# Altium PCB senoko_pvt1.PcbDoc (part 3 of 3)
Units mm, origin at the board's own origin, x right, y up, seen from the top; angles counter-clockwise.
Board outline 124.5 x 41 mm, 4 copper layers (Top Layer, Internal Plane 1, Internal Plane 2, Bottom Layer), stack 1.671 mm thick; 226 components, 139 nets, 1479 pads, 355 vias.
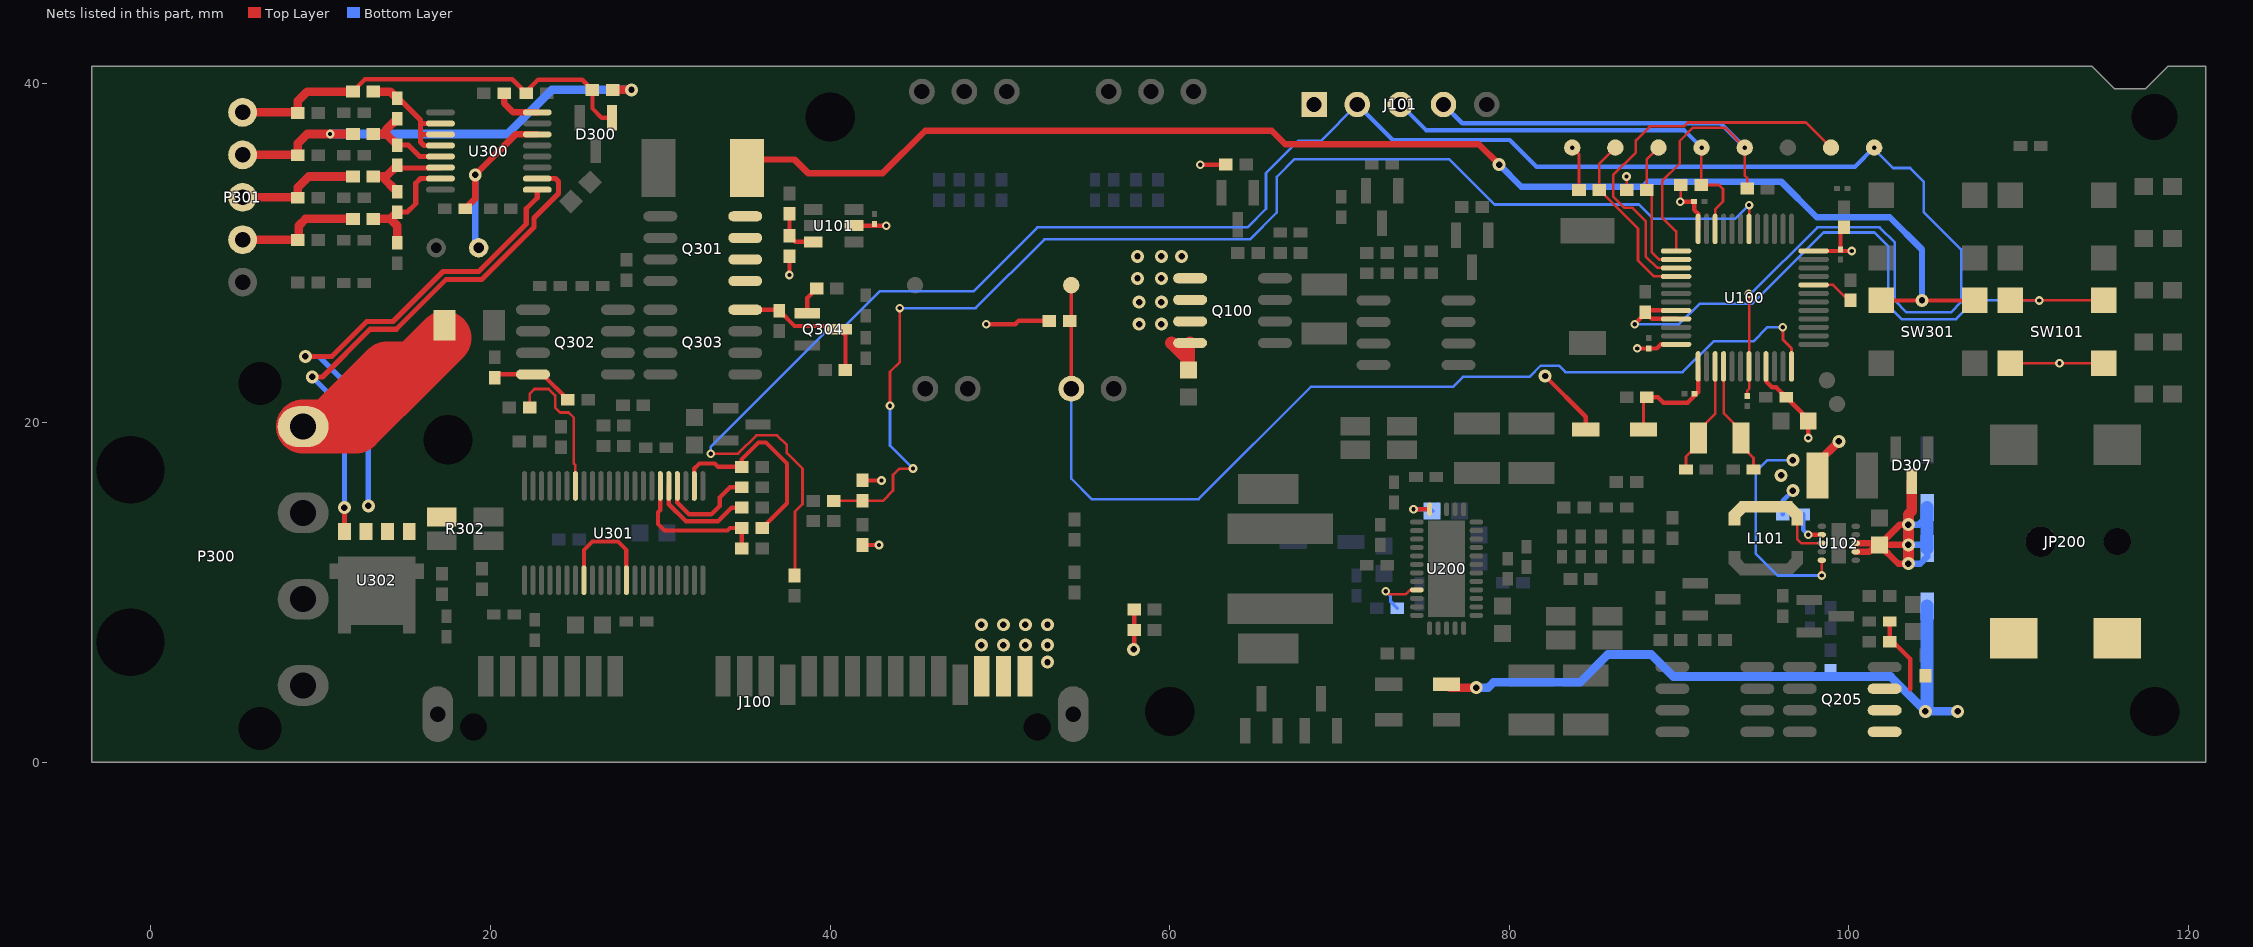
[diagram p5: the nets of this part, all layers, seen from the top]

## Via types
v1: diameter 0.508, hole 0.254, Top Layer to Bottom Layer, tented both sides, 187 vias
v2: diameter 0.762, hole 0.381, Top Layer to Bottom Layer, tented both sides, 155 vias
v3: diameter 0.66, hole 0.33, Top Layer to Bottom Layer, tented top, 9 vias
v4: diameter 0.5, hole 0.2, Top Layer to Bottom Layer, 3 vias
v5: diameter 0.66, hole 0.33, Top Layer to Bottom Layer, tented both sides, 1 vias

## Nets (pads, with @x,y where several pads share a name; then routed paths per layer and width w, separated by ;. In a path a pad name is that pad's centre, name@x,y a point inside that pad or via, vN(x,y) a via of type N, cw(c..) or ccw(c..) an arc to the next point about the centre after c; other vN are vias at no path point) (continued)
NetQ301_5: Q301.5 Q301.6 Q301.7 Q301.8 R300.1 SW301.1 SW301.2 | length 82.4
  Top Layer w0.254: SW301.2@101.9,27.2 SW301.1@107.4,27.2
  Top Layer w0.381: R300.1@35.1,35 35.4,35 35.9,35.5 37.9,35.5 38.7,34.7 43.1,34.7 45.6,37.2 66,37.2 66.8,36.4 78.2,36.4 v2(79.4,35.2)
  Bottom Layer w0.381: v2(79.4,35.2) 80.7,33.9 87.9,33.9 88.2,34.2 96,34.2 98.1,32.1 102.4,32.1 104.3,30.2 v2(104.3,27.2)
NetQ302_4: Q302.4 R303.2 R307.1 | length 5
  Top Layer w0.254: R303.2@20.25,22.65 20.445,22.845 Q302.4@22.5,22.845 23.065,22.845 24.55,21.36 R307.1@24.55,21.35
NetQ303_4: Q303.4 Q304.3 R304.1 R308.1 | length 8.6
  Top Layer w0.254: Q303.4@35,26.655 36.945,26.655 R304.1@37,26.6 37.9,25.7 40.35,25.7 Q304.3@40.55,25.5 40.9,25.15 R308.1@40.9,23.1
NetQ304_1: Q304.1 R311.1 | length 1.7
  Top Layer w0.254: Q304.1@38.65,26.45 38.65,27.35 R311.1@39.2,27.9
NetR102_2: R102.2 U102.7 | length 2.1
  Top Layer w0.254: v1(97.6,13.4) U102.7@98.4,13.4
  Bottom Layer w0.254: R102.2@97.3,14.6 97.3,13.7 v1(97.6,13.4)
NetR116_2: R116.2 U100.20 | length 2.6
  Top Layer w0.152: U100.20@97.917,28.114 99.061,28.114 99.975,27.2 R116.2@100.1,27.2
NetR117_2: R117.2 R118.1 U101.6 | length 2.8
  Top Layer w0.254: R118.1@37.6,32.3 R117.2@37.6,31 37.95,30.65 U101.6@39,30.65
NetR211_1: R211.1 U200.26 | length 3.3
  Top Layer w0.152: v1(72.725,10.075) 72.9,9.9 73.9,9.9 74.15,10.15 U200.26@74.55,10.15
  Bottom Layer w0.203: v1(72.725,10.075) 73,9.8 73,9.475 R211.1@73.4,9.075
NetR319_2: R319.2 R322.2 U301.2 | length 12.5
  Top Layer w0.254: U301.2@32,16.275 32,17.3 32.3,17.6 33.2,17.6 33.4,17.4 R319.2@34.8,17.4 34.8,17.854 35.779,18.833 36.221,18.833 37.458,17.596 37.458,15.258 R322.2@36,13.8
NetR320_2: R320.2 U301.4 | length 6
  Top Layer w0.254: U301.4@31,16.275 31,15.3 31.7,14.6 33,14.6 33.5,15.1 33.5,15.6 34.1,16.2 R320.2@34.8,16.2
NetR321_2: R321.2 U301.5 | length 6.1
  Top Layer w0.254: U301.5@30.5,16.275 30.5,15.2 31.506,14.194 33.394,14.194 34.2,15 R321.2@34.8,15
NetR322_1: R322.1 R323.1 U301.6 | length 8.7
  Top Layer w0.254: U301.6@30,16.275 30,14.854 29.867,14.721 29.867,14.033 30.25,13.65 33.95,13.65 34.1,13.8 R322.1@34.8,13.8 R323.1@34.8,12.6
NetR338_2: R338.2 U301.16 | length 8.7
  Top Layer w0.152: R338.2@22.3,20.9 22.3,21.7 22.583,21.983 23.425,21.983 23.8,21.607 23.8,20.9 24.1,20.6 24.6,20.6 24.9,20.3 24.9,17.6 25,17.5 U301.16@25,16.275
NetR339_1: R339.1 U300.16 | length 2.8
  Top Layer w0.381: R339.1@20.8,39.4 20.8,38.8 21.325,38.275 U300.16@22.75,38.275
NetU301_30: U301.30 U301.35 | length 6.5
  Top Layer w0.254: U301.30@25.5,10.725 25.5,12.5 26,13 27.5,13 28,12.5 U301.35@28,10.725
P2_CD: C309.1 J300.1 U300.14 | length 11.3
  Top Layer w0.381: C309.1@18.5,32.6 19.1,33.2 v2(19.1,34.6) 21.475,36.975 U300.14@22.75,36.975
  Bottom Layer w0.381: v2(19.1,34.6) 19.1,30.7 J300.1@19.5,30.3
P2_OUT: U300.10 U302.4 | length 31.2
  Top Layer w0.305: v2(9.5,22.7) 10.1,22.7 12.9,25.5 14.447,25.5 17.389,28.443 19.489,28.443 22.557,31.511 22.557,32.057 24,33.5 24,34.2 23.825,34.375 U300.10@22.75,34.375 ; U302.4@11.395,13.595 v2(11.395,14.995)
  Bottom Layer w0.305: v2(9.5,22.7) 11.395,20.805 v2(11.395,14.995)
P2_PCKN: R302.2 U300.9 U302.1 U302.2 U302.3 | length 29.3
  Top Layer w0.305: v2(9.1,23.9) 10.653,23.9 12.711,25.957 14.257,25.957 17.2,28.9 19.3,28.9 22.1,31.7 22.1,32.6 22.75,33.25 U300.9@22.75,33.725
  Bottom Layer w0.305: v2(9.1,23.9) 9.9,23.9 12.8,21 v2(12.8,15.1)
P2_VC1: C304.1 R306.2 U300.2 U300.3 U300.4 | length 8.4
  Top Layer w0.305: C304.1@14.5,39.1 14.6,39.1 15.875,37.825 15.875,37.625 ; U300.4@17.05,36.325 16.075,36.325 15.875,36.525 15.875,37 ; U300.3@17.05,36.975 15.9,36.975 15.875,37 ; U300.2@17.05,37.625 15.875,37.625 ; 15.875,37 15.875,37.625
  Top Layer w0.508: R306.2@13.1,39.5 14.1,39.5 C304.1@14.5,39.1
P2_VC2: C304.2 C306.1 R310.2 U300.5 | length 5.7
  Top Layer w0.305: C306.1@14.5,36.35 15.15,36.35 15.825,35.675 U300.5@17.05,35.675
  Top Layer w0.508: R310.2@13.1,37 13.85,37 ; C306.1@14.5,36.35 13.85,37 ; C304.2@14.5,37.9 13.85,37.25 13.85,37
P2_VC3: C306.2 C308.1 R312.2 U300.6 | length 5.1
  Top Layer w0.305: C306.2@14.5,35.15 14.65,35 17.025,35 U300.6@17.05,35.025
  Top Layer w0.508: C308.1@14.5,33.6 13.6,34.5 13.85,34.5 C306.2@14.5,35.15
P2_VC4: C308.2 C311.1 R318.2 U300.7 | length 7.2
  Top Layer w0.305: C308.2@14.5,32.4 15.1,32.4 15.6,32.9 15.6,34.1 15.875,34.375 U300.7@17.05,34.375
  Top Layer w0.508: R318.2@13.1,32 14.1,32 ; C311.1@14.5,30.6 14.5,31.6 14.1,32 ; C308.2@14.5,32.4 14.1,32
P3.3V_UC: C102.1 C103.1 C104.1 C112.2 C113.2 C115.1 C118.1 C222.1 D100.1 J101.1 L101.2 R102.1 R108.1 R109.2 R110.2 R111.2 R112.2 R113.2 R117.1 R119.2 R121.2 R225.1 R226.1 SW101.1 SW101.2 TP100.1 U100.9 U100.24 U100.36 U100.48 U101.2 U102.8 U102.10 U200.17 | length 62.4
  Top Layer w0.152: v1(83.7,36.2) 84.1,35.8 R113.2@84.1,33.7 ; R112.2@86.9,33.7 v1(86.9,34.5) ; v1@90.05,33.025 90.1,33.075 R111.2@90.1,34 ; L101.2@96.95,14.325 96.95,13.15 97.2,12.9 U102.8@98.4,12.9 ; v1(98.4,11) U102.10@98.4,11.9 ; SW101.1@109.5,23.5 SW101.2@115,23.5
  Top Layer w0.254: v1@37.575,28.675 v1(37.6,28.7) R117.1@37.6,29.8 ; U101.2@41.4,31.6 v1(43.3,31.6) ; R109.2@41.9,12.8 v1(42.875,12.8) ; R110.2@41.9,16.6 v1(43.025,16.6) ; v1(49.2,25.8) 50.9,25.8 51.1,26 R121.2@52.9,26 ; v2(57.875,6.65) 57.9,6.675 R225.1@57.9,7.8 R226.1@57.9,9 ; v1(61.8,35.2) R108.1@63.3,35.2 ; v1(74.35,14.9) U200.17@75.3,14.9 ; v2(82.1,22.75) 84.5,20.35 D100.1@84.5,19.6 D100.1@84.775,19.6 ; v1(87.525,24.375) 88.675,24.375 88.914,24.614 U100.48@89.817,24.614 ; v1@90.05,33.025 v1(90.055,33.02) C103.1@90.88,33.02 90.88,32.545 91.117,32.308 U100.36@91.117,31.414 ; U100.9@95.117,23.314 95.117,22.438 95.475,22.079 95.721,22.079 C112.2@96.3,21.5 97.6,20.2 C113.2@97.6,20.1 v1(97.6,19.1) ; U100.24@97.917,30.114 v1(100.164,30.114) v1@100.175,30.125 ; C104.1@99.5,30.2 R119.2@99.5,31.3
  Top Layer w0.508: C118.1@98.15,16.9 98.15,17.65 v2(99.4,18.9)
  Bottom Layer w0.152: v2(96.7,17.8) 95.2,17.8 94.5,17.1 94.5,12.3 95.8,11 v1(98.4,11)
  Bottom Layer w0.254: v1(74.35,14.9) 75.35,14.9 C222.1@75.45,14.8 ; R102.1@96.1,14.6 96.1,15.4 v2(96.7,16)
  other v1: 112.4,23.5
  other v2: 96,16.9
PM_JRST: R113.1 TP101.1 U100.40 | length 10.6
  Top Layer w0.152: TP101.1@86.24,36.2 85.3,35.26 R113.1@85.3,33.7 87.575,31.425 87.575,29.55 88.511,28.614 U100.40@89.817,28.614
PM_JTCK: J101.4 R114.2 TP104.1 U100.37 | length 33.1
  Top Layer w0.152: U100.37@89.817,30.114 89.817,31.258 89,32.075 89,34.225 90.025,35.25 90.025,36.575 90.825,37.375 92.685,37.375 v1(93.86,36.2) 93.86,34.565 94,34.425 R114.2@94,33.8
  Bottom Layer w0.254: J101.4@76.12,38.74 77.224,37.636 92.424,37.636 v1(93.86,36.2)
PM_JTDI: R112.1 TP102.1 U100.38 | length 8.2
  Top Layer w0.152: TP102.1@88.78,36.2 88.1,35.52 R112.1@88.1,33.7 88.375,33.425 88.375,30.05 88.811,29.614 U100.38@89.817,29.614
PM_JTDO: TP105.1 U100.39 | length 23.1
  Top Layer w0.152: U100.39@89.817,29.114 88.711,29.114 88.025,29.8 88.025,31.875 87.25,32.65 86.781,32.65 86.116,33.316 86.116,34.591 87.45,35.925 87.45,36.625 88.275,37.45 90.275,37.45 90.505,37.68 97.46,37.68 TP105.1@98.94,36.2
PM_JTMS: J101.3 R111.1 TP103.1 U100.34 | length 24.9
  Top Layer w0.152: v1(91.32,36.2) 91.3,36.18 R111.1@91.3,34 92.35,34 92.583,33.767 92.583,33.033 92.125,32.575 92.125,31.422 U100.34@92.117,31.414
  Bottom Layer w0.254: J101.3@73.58,38.74 75.091,37.229 90.291,37.229 v1(91.32,36.2)
PM_NRST: C114.1 J101.2 R103.1 TP106.1 U100.7 | length 130.1
  Top Layer w0.152: v1(32.975,18.175) 34.575,18.175 35.65,19.25 36.875,19.25 37.45,18.675 37.45,18.218 38.371,17.296 38.371,15.202 37.93,14.761 R103.1@37.93,11.087 ; C114.1@94.008,21.582 94.008,21.883 94.117,21.992 U100.7@94.117,23.314 94.117,27.583 v1(94.1,27.6)
  Bottom Layer w0.152: v1(32.975,18.175) 32.975,18.595 39.96,25.58 40.755,25.58 42.91,27.735 48.446,27.735 52.212,31.5 64.565,31.5 65.665,32.6 65.665,34.703 67.563,36.6 68.9,36.6 J101.2@71.04,38.74 ; v1(94.1,27.6) 94.23,27.6 98.135,31.505 101.795,31.505 102.7,30.6 102.7,27.2 103.4,26.5 106,26.5 106.6,27.1 106.6,30.2 104.4,32.4 104.4,34.2 103.6,35 102.6,35 101.48,36.12 v1(101.48,36.2)
  Bottom Layer w0.254: J101.2@71.04,38.74 73.13,36.65 80.025,36.65 81.6,35.075 100.355,35.075 v1(101.48,36.2)
PM_OSC32_IN: C110.1 U100.3 Y100.2 | length 7
  Top Layer w0.152: C110.1@90.273,17.252 C110.1@90.4,17.252 ; C110.1@90.4,17.25 C110.1@90.4,17.252 ; C110.1@90.512,17.252 C110.1@90.4,17.252 ; U100.3@92.117,23.314 92.117,20.517 91.15,19.55 Y100.2@91.15,19.1 91.15,18.75 90.4,18 C110.1@90.4,17.252
PM_OSC32_OUT: C111.1 U100.4 Y100.1 | length 6.8
  Top Layer w0.152: U100.4@92.617,23.314 92.617,20.583 93.65,19.55 Y100.1@93.65,19.1 93.65,18.65 94.375,17.925 C111.1@94.375,17.25 ; C111.1@94.223,17.286 C111.1@94.257,17.252
PM_REFLASH_ALRT: R106.2 SW101.3 SW101.4 U100.44 U100.45 | length 41
  Top Layer w0.152: SW101.3@109.5,27.2 SW101.4@115,27.2
  Top Layer w0.254: v1(87.375,25.8) 88,26.425 R106.2@88,26.5 ; U100.45@89.817,26.114 88.386,26.114 R106.2@88,26.5 ; U100.44@89.817,26.614 88.114,26.614 R106.2@88,26.5
  Bottom Layer w0.152: v1(87.375,25.8) 90,25.8 91.2,27 94.3,27 98.5,31.2 101.5,31.2 102.3,30.4 102.3,26.9 103.1,26.1 106.3,26.1 107.4,27.2 v1(111.2,27.2)
PM_TO_HOST_UART: R100.1 R110.1 U100.30 | length 74.3
  Top Layer w0.152: R100.1@40.2,15.4 R110.1@41.9,15.4 43.1,15.4 43.7,16 43.7,16.925 44.075,17.3 v1(44.875,17.3) ; v1(43.525,21) 43.525,23 44.1,23.575 v1(44.1,26.75) ; U100.30@94.117,31.414 v1(94.117,32.817)
  Bottom Layer w0.152: v1(43.525,21) 43.525,18.65 v1(44.875,17.3) ; v1(44.1,26.75) 48.569,26.75 52.619,30.8 64.728,30.8 66.3,32.372 66.3,34.475 67.35,35.525 76.45,35.525 79.125,32.85 87.625,32.85 88.475,32 93.3,32 v1(94.117,32.817)
PM_VBAT: C109.1 D100.2 R107.2 U100.1 | length 7
  Top Layer w0.152: D100.2@87.9,19.6 87.9,21.3 R107.2@88.1,21.5 ; C109.1@90.914,21.658 C109.1@90.914,21.707
  Top Layer w0.254: R107.2@88.1,21.5 88.75,21.5 89.08,21.17 90.497,21.17 91.117,21.789 U100.1@91.117,23.314
PWR_TO_HOST: C101.1 J100.1 J100.2 J100.3 Q100.5 Q100.6 Q100.7 Q100.8 | length 3.1
  Top Layer w0.762: 60.1,24.7 61.1,23.7 ; C101.1@61.1,23.1 61.1,23.7 ; Q100.8@61.2,24.695 61.1,24.595 61.1,23.7
  other v2: 52.8,5.9 48.9,6.9 50.2,6.9 51.5,6.9 52.8,6.9 48.9,8.1 50.2,8.1 51.5,8.1 52.8,8.1 58.2,25.8 59.5,25.8 58.2,27.1 59.5,27.1 58.1,28.5 59.5,28.5 58.1,29.8 59.5,29.8 60.7,29.8
RAW_ACIN: C204.2 D101.1 D201.1 JP200.1 Q205.1 Q205.2 Q205.3 R208.1 R213.1 R214.1 | length 43.2
  Top Layer w0.254: C204.2@102.4,8.3 R208.1@102.4,7.1 102.6,7.1 103.6,6.1 103.6,4.3
  Top Layer w0.508: D201.1@76.3,4.6 76.5,4.4 v2(78.05,4.4)
  Bottom Layer w0.508: v2(78.05,4.4) 78.756,4.4 79.063,4.707 84.157,4.707 85.8,6.35 88.35,6.35 89.65,5.05 102.45,5.05 v2(104.5,3) v2(106.4,3)
  Bottom Layer w0.762: v2(104.5,3) 104.6,3.1 D101.1@104.6,9.2
UC_BOOTSTRAP: C117.1 D101.2 D307.3 D308.2 U102.2 U102.3 | length 20.9
  Top Layer w0.381: U102.2@100.4,12.4 101.2,12.4 101.7,12.9 U102.3@100.4,12.9 ; v2(103.5,11.7) 102.9,11.7 C117.1@101.8,12.8 ; v2(103.5,12.8) C117.1@101.8,12.8 ; v2(103.5,14) 103,14 C117.1@101.8,12.8
  Top Layer w0.635: v2(103.5,11.7) v2(103.5,14) 103.5,14.6 103.7,14.8 D307.3@103.7,16.55
  Bottom Layer w0.381: v2(103.5,11.7) 104.2,11.7 104.6,12.1 D101.2@104.6,12.6 104.4,12.8 v2(103.5,12.8) ; v2(103.5,14) 104.1,14 104.6,14.5 D308.2@104.6,15
  Bottom Layer w0.762: D101.2@104.6,12.6 D308.2@104.6,15
USART2_TX_ADC2: J103.1 P102.1 R121.1 U100.12 | length 60.8
  Top Layer w0.178: v1(96.1,25.614) 96.1,24.9 96.617,24.383 U100.12@96.617,23.314
  Top Layer w0.203: P102.1@54.2,22 J103.1@54.2,28.1
  Bottom Layer w0.152: P102.1@54.2,22 54.2,16.7 55.4,15.5 61.693,15.5 68.302,22.109 76.678,22.109 77.264,22.695 81.183,22.695 81.847,23.36 82.917,23.36 83.3,22.976 90.207,22.976 92.026,24.795 94.364,24.795 95.183,25.614 v1(96.1,25.614)
VBAT: F300.1 P300.1 | length 17
  Top Layer w3.175: P300.1@8.96,19.77 10.47,19.77 ; F300.1@17.3,25 15.5,23.2 ; 10.47,19.77 12.07,19.77 15.5,23.2 ; 10.47,19.77 13.9,23.2 15.5,23.2
VC1: D300.1 P301.1 R305.2 R306.1 R309.1 R313.1 | length 25.3
  Top Layer w0.254: R306.1@11.9,39.5 11.9,39.521 12.6,40.221 21.279,40.221 R309.1@22.1,39.4 22.1,39.5 22.8,40.2 25.4,40.2 R305.2@26,39.6 26,38.5 26.55,37.95 D300.1@27.15,37.95
  Top Layer w0.508: P301.1@5.4,38.275 8.625,38.275 R313.1@8.65,38.25 8.65,38.95 9.2,39.5 R306.1@11.9,39.5
VC2: P301.2 R305.1 R310.1 R314.1 | length 27.4
  Top Layer w0.508: P301.2@5.4,35.775 8.625,35.775 R314.1@8.65,35.75 8.65,36.45 9.2,37 v1(10.55,37) R310.1@11.9,37 ; R305.1@27.2,39.6 v2(28.3,39.6)
  Bottom Layer w0.508: v1(10.55,37) 21,37 23.6,39.6 v2(28.3,39.6)
VC3: P301.3 R312.1 R315.1 | length 7.4
  Top Layer w0.508: P301.3@5.4,33.275 8.625,33.275 R315.1@8.65,33.25 8.65,33.85 9.3,34.5 R312.1@11.9,34.5
VC4: P301.4 R316.1 R318.1 | length 7.5
  Top Layer w0.508: P301.4@5.4,30.775 8.625,30.775 R316.1@8.65,30.75 8.7,30.8 8.7,31.6 9.1,32 R318.1@11.9,32
pads on no net: D300.2 D301.2 D307.2 J100.0 J100.7 J100.8 J100.9 JP200.0 P300.0 P300.4 U100.2 U100.5 U100.6 U100.11 U100.13 U100.15 U100.19 U100.26 U100.41 U100.42 U100.43 U100.46 U300.1 U300.11 U300.15 U301.12 U301.17 U301.19

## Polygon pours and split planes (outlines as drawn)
GND on Bottom Layer "bottom - GND" (solid, remove dead copper, pour order 2): 111.875,43.625 1.375,43.625 -5.8,42.4 -5.2,-2 0.925,-3.05 120.875,-3.05 124.8,0.875 124.8,39.975 121.25,43.525 111.15,43.525
GND on Top Layer "bottom - GND" (solid, remove dead copper, pour order 4): 90.45,-3.225 119.475,-3.225 124.375,1.675 124.375,42 121.775,44.6 1.65,44.6 -7,41.8 -7.6,-2.2 0.75,-4.475 1.9,-3.325 91.875,-3.325
GND on Internal Plane 1 (split plane): 87.321,14.357 87.321,13.868 87.182,13.729 86.793,13.729 86.604,13.918 86.604,14.282 86.818,14.496 87.182,14.496
GND on Internal Plane 1 (split plane): 82.021,12.957 82.021,12.568 81.732,12.279 81.493,12.279 81.179,12.593 81.179,12.882 81.389,13.093 81.886,13.093
GND on Internal Plane 1 (split plane): 76.396,17.657 76.396,16.45 76.396,15.443 75.127,14.173 75.104,14.14 75.096,14.1 75.096,9.925 75.104,9.885 75.127,9.852 75.427,9.552 75.46,9.529 75.5,9.521 75.882,9.521 76.221,9.182 76.221,8.618 75.957,8.354 70.743,8.354 69.254,9.843 69.254,11.5 69.254,14.532 72.893,18.171 75.882,18.171
GND on Internal Plane 1 (split plane): 37.521,18.157 37.521,12.368 36.607,11.454 34.75,11.454 34.71,11.446 34.677,11.423 30.282,7.029 28.743,7.029 27.348,8.423 27.315,8.446 27.275,8.454 18.275,8.454 18.235,8.446 18.202,8.423 16.532,6.754 15.493,6.754 15.229,7.018 15.229,8.282 18.293,11.346 20.4,11.346 20.408,11.348 21.55,11.348 21.589,11.356 21.622,11.378 22.272,12.028 22.294,12.061 22.302,12.1 22.302,13.205 23.118,14.021 26.15,14.021 26.19,14.029 26.223,14.052 27.723,15.552 27.734,15.569 27.746,15.585 27.754,15.625 27.754,20.557 28.968,21.771 33.907,21.771
GND on Internal Plane 1 (split plane): 120.49,0.51 -2.99,0.51 -2.99,40.49 114.089,40.49 115.264,39.314 115.341,39.251 115.43,39.203 115.525,39.174 115.625,39.165 117.475,39.165 117.575,39.174 117.67,39.203 117.759,39.251 117.836,39.314 119.011,40.49 120.49,40.49
no net on Internal Plane 2 (split plane): 98.998,11.258 98.998,10.742 98.758,10.502 98.142,10.502 97.902,10.742 97.902,11.258 98.142,11.498 98.758,11.498
CHG_SYS on Internal Plane 2 (split plane): 72.477,25.877 72.494,25.866 72.51,25.854 72.55,25.846 77.482,25.846 82.027,21.302 82.044,21.291 82.06,21.279 82.1,21.271 84.532,21.271 85.296,20.507 85.296,17.4 85.304,17.36 85.327,17.327 86.121,16.532 86.121,14.918 85.077,13.873 85.054,13.84 85.046,13.8 85.046,10.225 85.054,10.185 85.077,10.152 87.546,7.682 87.546,4.943 87.082,4.479 78.975,4.479 78.935,4.471 78.902,4.448 77.882,3.429 75.543,3.429 74.429,4.543 74.429,7.482 74.948,8.002 74.959,8.019 74.971,8.035 74.979,8.075 74.979,15.025 74.971,15.065 74.948,15.098 74.623,15.423 74.59,15.446 74.55,15.454 71.718,15.454 64.904,22.268 64.904,24.757 67.493,27.346 71.007,27.346
PWR_TO_HOST on Internal Plane 2 (split plane): 62.446,29.432 62.446,22.418 55.302,15.273 55.279,15.24 55.271,15.2 55.271,7.168 53.307,5.204 48.468,5.204 48.329,5.343 48.329,11.532 49.823,13.027 49.846,13.06 49.854,13.1 49.854,27.482 53.093,30.721 61.157,30.721
P3.3V_UC on Internal Plane 2 (split plane): 120.49,0.51 -2.99,0.51 -2.99,40.49 114.089,40.49 115.264,39.314 115.341,39.251 115.43,39.203 115.525,39.174 115.625,39.165 117.475,39.165 117.575,39.174 117.67,39.203 117.759,39.251 117.836,39.314 119.011,40.49 120.49,40.49

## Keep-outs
Keep-Out Layer:
  the board outline again, w1
  text "Route board on centerline of this outline" at 98.2,-3.1 h0.76

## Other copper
Top Layer:
  rectangle net P2_PCKN: 12.3,13.9 16.6,15.6
  rectangle net BAT_PGND: 9,8 12.3,12.2
  rectangle net NetL200_2: 64.1,14.1 67.5,15.6
  rectangle net NetC300_2: 20.2,23.8 22.2,27
  rectangle net NetD301_1: 27.8,22.5 29.7,27
  rectangle net NetD301_1: 30.5,22.5 33.2,27
  rectangle net NetD301_1: 31.3,26.9 33.2,32.4
  rectangle net NetD301_1: 30,29.4 32.3,32.4
  rectangle net NetQ301_5: 34.3,28.1 36.6,36.7
  rectangle net GND: 18.4,13.8 22.1,16.5
  rectangle net GND: 21,12.6 23.3,15.1
  rectangle net GND: 20,15.4 22.1,17.8
  rectangle net BAT_PROTECTED: 35,22.5 38.8,25.4
  rectangle net RAW_ACIN: 108.3,2.7 114.9,8.3
  rectangle net NetQ205_5: 94.6,1.5 97.2,5.9
  rectangle net CHG_SYS: 81.3,4.6 84.5,6.9
  rectangle net CHG_SYS: 80.3,5.5 81.9,9.7
  rectangle net CHG_SYS: 78.3,9 79.2,10.2
  rectangle net CHG_SYS: 79.1,8.6 81.1,9.7
  rectangle net GND: 78.9,0.7 86.8,4.2
  rectangle net NetC206_2: 64,7.1 74.55,9.65
  rectangle net NetC206_2: 74.1,7.1 75.9,7.8
  rectangle net BAT_PROTECTED: 76.9,19.8 79.3,27.5
  rectangle net BAT_PROTECTED: 72.8,19.6 82.7,21.4
  rectangle net CHG_SYS: 66.7,24.375 71.9,27.2
  rectangle net CHG_SYS: 66.7,24.4 67.4,27.5
  rectangle net PWR_TO_HOST: 57.6,24.4 61.2,30.4
  rectangle net GND: 76.6,16.1 84.7,18.8
  rectangle net GND: 78.7,15.2 82,16.6
  rectangle net GND: 44.7,5.6 48.1,8.8
  rectangle net GND: 37,5.6 40.5,8.8
  rectangle net PWR_TO_HOST: 48.5,5.5 53.3,8.6
  rectangle net GND: 106.9,17.1 118.8,20.9
  rectangle net GND: 76.15,6.1 80.1,8.1
  rectangle net GND: 78,7.65 78.925,8.8
  rectangle net GND: 76.15,5.275 79.75,6.325
  rectangle net GND: 76.15,7.9 78.1,8.8
  rectangle net CHG_SYS: 67.175,22.95 70.75,25.15
  rectangle net CHG_SYS: 65.175,22.95 67.375,24.675
  rectangle net P3.3V_UC: 95.6,14.7 97.6,18.2
  rectangle net RAW_ACIN: 102.1,1.3 114.9,4.8
  rectangle net RAW_ACIN: 105.3,4.4 108.7,6.2
  rectangle net NetC205_2: 86.2,5.6 89.3,7.7
  rectangle net NetC205_2: 87.2,2.5 89.3,6.1
  pour cut-out: 74.45,18.2 72.875,18.2 69.125,14.45 69.125,9.65 70.65,8.125 87.875,8.125 90.675,10.925 90.675,15.15 90.25,15.575 82.825,15.575 82.075,14.825 77.35,14.825 76.325,15.85 76.325,17.775 75.825,18.275 75.775,18.225 74,18.225
  pour cut-out: 15.1,6.975 15.475,6.6 17.425,6.6 18.025,7.2 32.45,7.2 37.45,12.2 37.45,18.15 33.85,21.75 28.825,21.75 27.45,20.375 27.45,15.4 26.35,14.3 24.5,14.3 24.025,13.825 24.025,12.725 23.475,12.175 16.4,12.175 15.1,10.875
  pour cut-out: 29.5,40 29.5,38.7 33,38.7 33,40
  text "1" at 29.8,39 h0.76
Bottom Layer:
  pour cut-out: 88.9,8.4 90.775,10.275 90.775,15.075 90.325,15.525 86.325,15.525 85.525,14.725 78.875,14.725 76.3,17.3 76.3,17.775 75.85,18.225 73.125,18.225 69.2,14.3 69.2,9.625 70.425,8.4
  pour cut-out: 33.7,21.775 28.825,21.775 23.7,16.65 23.7,12.8 23,12.1 16.5,12.1 14.975,10.575 14.975,7.1 15.525,6.55 17.35,6.55 18,7.2 32.175,7.2 37.5,12.525 37.5,18.125 33.875,21.75 33.55,21.75
  pour cut-out: 29.5,38.7 33,38.7 33,40 29.5,40
  text "4" at 32.2,39 h0.76
Internal Plane 1 (plane layer: these items are gaps in the copper):
  rectangle: 29.5,38.7 30.2,40
  rectangle: 31.1,38.7 33,40
  lines w0.2: 20.4,11.45 21.55,11.45 22.2,12.1 22.2,13.25
  lines w0.203: 20.4,11.45 18.25,11.45 15.125,8.325 15.125,6.975 15.45,6.65 16.575,6.65 18.275,8.35 24.95,8.35 27.275,8.35 28.7,6.925 30.325,6.925 34.75,11.35 36.65,11.35 37.625,12.325 37.625,18.2 33.95,21.875 28.925,21.875 27.65,20.6 27.65,15.625 26.15,14.125 23.075,14.125 22.2,13.25 ; 69.15,9.8 69.15,11.5 69.15,14.575 72.85,18.275 75.925,18.275 76.5,17.7 76.5,16.45 76.5,15.4 75.2,14.1 75.2,9.925 75.5,9.625 75.925,9.625 76.325,9.225 76.325,8.575 76,8.25 74.9,8.25 70.7,8.25 69.15,9.8 ; 81.075,12.55 81.45,12.175 81.775,12.175 82.125,12.525 82.125,13 81.929,13.196 81.346,13.196 81.075,12.925 81.075,12.55 ; 86.5,13.875 86.75,13.625 87.225,13.625 87.425,13.825 87.425,14.4 87.225,14.6 86.775,14.6 86.5,14.325 86.5,13.875
  text "2" at 30.4,39 h0.76
Internal Plane 2 (plane layer: these items are gaps in the copper):
  rectangle: 29.5,38.7 31.1,40
  rectangle: 32,38.7 33,40
  lines w0.2: 97.8,10.7 98.1,10.4 98.8,10.4 99.1,10.7 99.1,11.3 98.8,11.6 98.1,11.6 97.8,11.3 97.8,10.7
  lines w0.203: 77.075,25.95 77.525,25.95 ; 77.525,25.95 72.55,25.95 71.05,27.45 67.45,27.45 64.8,24.8 64.8,22.225 71.675,15.35 74.55,15.35 74.875,15.025 74.875,8.075 74.325,7.525 74.325,4.5 75.5,3.325 77.925,3.325 78.975,4.375 81.075,4.375 87.125,4.375 87.65,4.9 87.65,7.725 85.15,10.225 85.15,13.8 86.225,14.875 86.225,16.575 85.4,17.4 85.4,20.55 84.575,21.375 82.1,21.375 77.525,25.95 ; 48.225,5.3 48.225,11.575 49.75,13.1 49.75,27.525 53.05,30.825 61.2,30.825 62.55,29.475 62.55,22.375 55.375,15.2 55.375,7.125 53.35,5.1 48.425,5.1 48.225,5.3
  text "3" at 31.3,39 h0.76

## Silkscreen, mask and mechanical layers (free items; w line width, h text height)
Top Overlay:
  lines w0.2: 44.167,9.469 ccw(c45.035,9.469) 45.035,8.602 52.295,8.602 ccw(c52.295,9.618) 53.311,9.618 53.311,14.19 ccw(c52.295,14.19) 52.295,15.206 45.183,15.206 ccw(c45.183,14.19) 44.167,14.19 44.167,9.469
  text "-" at 45.1,36 h0.8
  text "T" at 47.6,36 h0.8
  text "X" at 50.1,36 h0.8
  text "-" at 56.1,36 h0.8
  text "T" at 58.7,36 h0.8
  text "X" at 61.2,36 h0.8
  text "on/off" at 102.4,34.5 h0.9
  text "level" at 110.4,34.5 h0.9
  text "Senoko" at 44.8,33.7 h1.02
  text "Battery Board" at 44.8,32.2 h1.02
  text "PVT1-A" at 47.3,30.5 h0.76
  text "-" at 16.6,29.1 h0.51
  text "+" at 19.1,29.1 h0.51
  text "CD CLR" at 16.1,28.2 h0.71
  text "DAC" at 45.8,24.1 h0.76
  text "ADC" at 54.5,24.1 h0.76
  text "prime" at 102.6,21.5 h0.9
  text "reflash" at 109.4,21.5 h0.9
  text "+" at 45.3,18.7 h0.8
  text "-" at 47.8,18.7 h0.8
  text "+" at 53.9,18.7 h0.8
  text "-" at 56.4,18.7 h0.8
  text "Designed in" at 45.5,17.3 h0.76
  text "Singapore" at 45.5,15.9 h0.76
  text "07/14" at 53,15.9 h0.76
  text "Sutajio Ko-Usagi Pte Ltd" at 38.9,7.2 h0.76
Bottom Overlay:
  circle w0.127: c55.633,13.65 r0.583
  rectangle: 97.3,27 112,31.9
  text "S/N:" at 115.2,30.9 h0.76
  text "c bunnie@kosagi.com" at 55.9,13.4 h0.76
  text "CC3.0-BY-SA + XL1.0" at 56.2,11.9 h0.76
Mechanical 2:
  lines w0.1: -3.5,0 -3.5,35
Mechanical 3:
  lines w0.127: 130.952,-3.766 132.222,-5.036 ; 130.952,50.844 132.222,52.114 ; 133.492,-3.766 132.222,-5.036 ; 133.492,50.844 132.222,52.114 ; 156.352,-1.226 198.262,-1.226 ; 156.352,14.014 198.262,14.014 195.722,11.474 ; 156.352,35.604 198.262,35.604 195.722,33.064 ; 156.352,48.304 198.262,48.304 ; 157.622,11.474 160.162,14.014 ; 157.622,33.064 160.162,35.604 ; 158.892,0.044 160.162,-1.226 ; 158.892,11.474 161.432,14.014 ; 158.892,14.014 156.352,11.474 198.262,11.474 ; 158.892,33.064 161.432,35.604 ; 158.892,35.604 156.352,33.064 198.262,33.064 ; 158.892,47.034 160.162,48.304 ; 160.162,11.474 162.702,14.014 ; 160.162,33.064 162.702,35.604 ; 161.432,0.044 160.162,-1.226 ; 161.432,47.034 160.162,48.304 ; 162.702,11.474 165.242,14.014 ; 162.702,33.064 165.242,35.604 ; 163.972,11.474 166.512,14.014 ; 163.972,33.064 166.512,35.604 ; 165.242,11.474 167.782,14.014 ; 165.242,33.064 167.782,35.604 ; 167.303,49.592 168.573,50.862 ; 167.782,11.474 170.322,14.014 ; 167.782,33.064 170.322,35.604 ; 168.573,48.322 171.113,50.862 ; 169.052,11.474 171.592,14.014 ; 169.052,33.064 171.592,35.604 ; 169.843,48.322 171.113,49.592 ; 169.843,50.862 167.303,48.322 167.303,50.862 171.113,50.862 ; 170.322,11.474 172.862,14.014 ; 170.322,33.064 172.862,35.604 ; 171.113,48.322 171.113,50.862 ; 171.592,11.474 174.132,14.014 ; 171.592,33.064 174.132,35.604 ; 173.903,49.592 175.173,50.862 ; 174.132,11.474 176.672,14.014 ; 174.132,33.064 176.672,35.604 ; 175.173,48.322 177.713,50.862 ; 175.402,11.474 177.942,14.014 ; 175.402,33.064 177.942,35.604 ; 176.443,48.322 177.713,49.592 ; 176.443,50.862 173.903,48.322 173.903,50.862 177.713,50.862 ; 176.672,11.474 179.212,14.014 ; 176.672,33.064 179.212,35.604 ; 177.713,48.322 177.713,50.862 ; 177.942,11.474 180.482,14.014 ; 177.942,33.064 180.482,35.604 ; 180.482,11.474 183.022,14.014 ; 180.482,33.064 183.022,35.604 ; 181.752,11.474 184.292,14.014 ; 181.752,33.064 184.292,35.604 ; 185.562,11.474 188.102,14.014 ; 185.562,33.064 188.102,35.604 ; 186.832,11.474 189.372,14.014 ; 186.832,33.064 189.372,35.604 ; 190.642,-2.496 191.912,-1.226 ; 190.642,-1.226 190.642,-3.766 ; 190.642,11.474 193.182,14.014 ; 190.642,33.064 193.182,35.604 ; 190.642,49.574 191.912,50.844 ; 191.912,-3.766 194.452,-1.226 194.452,-3.766 190.642,-3.766 ; 191.912,11.474 194.452,14.014 ; 191.912,33.064 194.452,35.604 ; 191.912,48.304 194.452,50.844 ; 193.182,-3.766 194.452,-2.496 ; 193.182,-1.226 190.642,-3.766 ; 193.182,11.474 195.722,14.014 ; 193.182,33.064 195.722,35.604 ; 193.182,48.304 194.452,49.574 ; 193.182,50.844 190.642,48.304 190.642,50.844 194.452,50.844 ; 194.452,11.474 196.992,14.014 ; 194.452,33.064 196.992,35.604 ; 194.452,48.304 194.452,50.844 ; 196.992,11.474 198.262,12.744 ; 196.992,33.064 198.262,34.334 ; 132.222,-5.036 132.222,52.114 ; 160.162,-1.226 160.162,48.304 ; 156.352,12.744 157.622,14.014 156.352,12.744 ; 156.352,34.334 157.622,35.604 156.352,34.334 ; 161.432,11.474 163.972,14.014 161.432,11.474 ; 161.432,33.064 163.972,35.604 161.432,33.064 ; 166.512,11.474 169.052,14.014 166.512,11.474 ; 166.512,33.064 169.052,35.604 166.512,33.064 ; 172.862,11.474 175.402,14.014 172.862,11.474 ; 172.862,33.064 175.402,35.604 172.862,33.064 ; 179.212,11.474 181.752,14.014 179.212,11.474 ; 179.212,33.064 181.752,35.604 179.212,33.064 ; 183.022,11.474 185.562,14.014 183.022,11.474 ; 183.022,33.064 185.562,35.604 183.022,33.064 ; 184.292,11.474 186.832,14.014 184.292,11.474 ; 184.292,33.064 186.832,35.604 184.292,33.064 ; 188.102,11.474 190.642,14.014 188.102,11.474 ; 188.102,33.064 190.642,35.604 188.102,33.064 ; 189.372,11.474 191.912,14.014 189.372,11.474 ; 189.372,33.064 191.912,35.604 189.372,33.064
  text "Board name: Senoko PVT1A" at 144.922,76.244 h1
  text "Contact: bunnie@kosagi.com" at 144.922,73.704 h1
  text "No impedance control requirement" at 170.2,58 h0.76
  text "Silk: white" at 170.363,56.197 h0.76
  text "Soldermask: matte black" at 170.238,54.697 h0.76
  text "Material and thickness" at 129.682,54.654 h1.27
  text "Finish: Immersion gold" at 170.238,53.347 h0.76
  text "Plate 0.5 oz" at 144.922,49.574 h0.76
  text "Top-bottom pair" at 160.162,49.574 h0.76 r45
  text "Copper 1.0 oz" at 144.922,48.304 h0.76
  text "Total 1.5 oz" at 144.922,46.78 h0.76
  text "Prepreg" at 134.762,38.144 h0.76
  text "FR-4 0.1mm" at 144.922,38.144 h0.76
  text "Copper 1 oz" at 144.922,34.334 h0.76
  text "Plane" at 202.072,34.334 h0.76
  text "0.035mm" at 147.97,33.064 h0.76
  text "Core" at 134.762,22.904 h0.76
  text "FR-4 height as needed to meet overall height spec" at 144.922,22.904 h0.76
  text "Overall height: 1.58mm +/-10%" at 130.952,17.824 h0.76 r90
  text "Copper 1 oz" at 144.922,12.744 h0.76
  text "0.035mm" at 147.97,11.474 h0.76
  text "Plane" at 202.072,11.474 h0.76
  text "Prepreg" at 134.762,7.664 h0.76
  text "FR-4 0.1mm" at 144.922,7.664 h0.76
  text "Copper 1.0 oz" at 144.922,-2.496 h0.76
  text "Finish: Immersion gold" at 170.313,-3.403 h0.76
  text "Plate 0.5 oz" at 144.922,-3.766 h0.76
  text "Soldermask: green" at 170.188,-5.003 h0.76
  text "Total 1.5oz" at 145.081,-5.334 h0.76
  text "Silk: white" at 170.313,-6.603 h0.76
  text "Mech via: 10 mil hole / 20 mil pad smallest" at 144.772,-8.716 h0.76
  text "Route: 6mil / 6mil smallest" at 144.772,-11.256 h0.76
Drill Drawing:
  text ".LEGEND" at 134.63,1.28 h1.52
  text "Drill Drawing." at 134.63,-1.26 h1.52

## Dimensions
-3.5,41 to 121,41 on Mechanical 3
-3.5,0 to 0,41 on Mechanical 3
